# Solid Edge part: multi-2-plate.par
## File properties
Author: CADCIM
Template: Iso Part.par
Last saved by: Cadcim
Revision: 4
Application: Solid Edge
Accuracy: 0.990
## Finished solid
Body 1: solid body, 6 faces, 12 edges, 8 vertices.
  Faces by surface: plane 6
  Edges by curve: line 12
Bounding box of the edges (mm): 120.000 x 60.000 x 15.000, from (-60, -30, 0) to (60, 30, 15).
Planar faces by outward normal: +x 1, +y 1, +z 1, -x 1, -y 1, -z 1
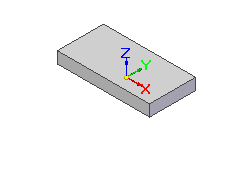
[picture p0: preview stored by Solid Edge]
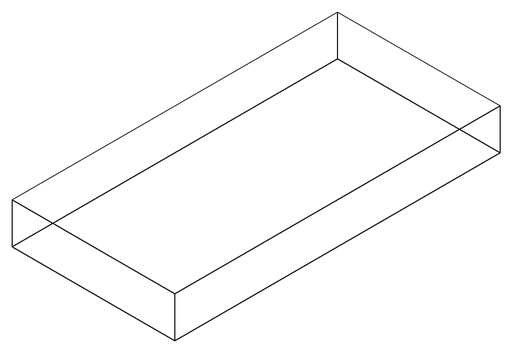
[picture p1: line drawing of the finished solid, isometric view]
